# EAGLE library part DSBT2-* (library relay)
DS-BT RELAYS 4,000 V BREAKDOWN VOLTAGE NAiS Source: http://www.mew-europe.com/.. en_ds_61005_0010.pdf
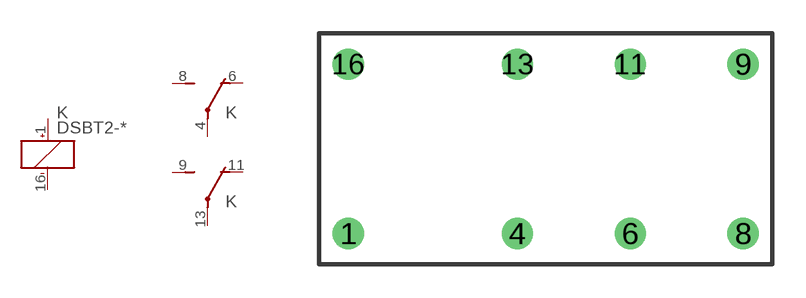
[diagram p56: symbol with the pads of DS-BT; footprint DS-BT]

Designator prefix K; gates 1=K+- 2=U 3=U

## DSBT2-M-2D-DC1.5V (OC_FARNELL: unknown; OC_NEWARK: unknown), DSBT2-M-2D-DC3V (OC_FARNELL: unknown; OC_NEWARK: unknown), DSBT2-M-2D-DC5V (OC_FARNELL: unknown; OC_NEWARK: unknown), DSBT2-M-2D-DC6V (OC_FARNELL: unknown; OC_NEWARK: unknown), DSBT2-M-2D-DC9V (OC_FARNELL: unknown; OC_NEWARK: unknown), DSBT2-M-2D-DC12V (OC_FARNELL: unknown; OC_NEWARK: unknown), DSBT2-M-2D-DC24V (OC_FARNELL: unknown; OC_NEWARK: unknown), DSBT2-S-DC1.5V (OC_FARNELL: unknown; OC_NEWARK: unknown), DSBT2-S-DC3V (MPN: DSBT2-S-DC3V; OC_FARNELL: unknown; OC_NEWARK: 11N4489), DSBT2-S-DC5V (OC_FARNELL: unknown; OC_NEWARK: unknown), DSBT2-S-DC6V (OC_FARNELL: unknown; OC_NEWARK: unknown), DSBT2-S-DC9V (OC_FARNELL: unknown; OC_NEWARK: unknown), DSBT2-S-DC12V (OC_FARNELL: unknown; OC_NEWARK: unknown), DSBT2-S-DC24V (OC_FARNELL: unknown; OC_NEWARK: unknown)  [DS-BT]
1  1:+  pas
4  2:P  pas
6  2:O  pas
8  2:S  pas
9  3:S  pas
11  3:O  pas
13  3:P  pas
16  1:-  pas

## Footprint DS-BT (pad centres in mm)
DS-BT RELAYS 4,000 V BREAKDOWN VOLTAGE NAiS Source: http://www.mew-europe.com/.. en_ds_61005_0010.pdf
drill 0.9 round: 1 -8.89,-3.81; 4 -1.27,-3.81; 6 3.81,-3.81; 8 8.89,-3.81; 9 8.89,3.81; 11 3.81,3.81; 13 -1.27,3.81; 16 -8.89,3.81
